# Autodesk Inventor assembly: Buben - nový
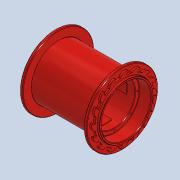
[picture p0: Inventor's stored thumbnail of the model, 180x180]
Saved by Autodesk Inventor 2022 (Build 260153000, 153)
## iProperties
Created: 2025-05
Part Number: Buben - nový
Document SubType Name: Assembly
Designer: jbart
Mass: 71047.9 g
Surface Area: 34761.7 cm^2
Volume: 71047.9 cm^3
Density: 1 g/cm^3
Author: jbart
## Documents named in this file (4)
- C:\Users\jbart\OneDrive\Dokumenty\Inventor\Převodovka navijáku\Buben - nový.iam
- C:\Users\jbart\OneDrive\Dokumenty\Inventor\Převodovka navijáku\Plášť bubnu.ipt
- C:\Users\jbart\OneDrive\Dokumenty\Inventor\Převodovka navijáku\Bočnice - levá.ipt
- C:\Users\jbart\OneDrive\Dokumenty\Inventor\Převodovka navijáku\Bočnice - pravá.ipt
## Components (3 placed, 3 different names)
1. Plášť bubnu:1 — Proti sobě:1, Proti sobě:2, Stejný směr:1, Proti sobě:3, Proti sobě:4, Stejný směr:2
2. Bočnice - levá:1 — Proti sobě:1, Proti sobě:2, Stejný směr:1
3. Bočnice - pravá:1 — Proti sobě:3, Proti sobě:4, Stejný směr:2
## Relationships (6: Mate 4, Flush 2)
- Proti sobě:1 [Mate]: Plášť bubnu:1 ↔ Bočnice - levá:1
- Proti sobě:2 [Mate]: Plášť bubnu:1 ↔ Bočnice - levá:1
- Stejný směr:1 [Flush]: Plášť bubnu:1 ↔ Bočnice - levá:1
- Proti sobě:3 [Mate]: Plášť bubnu:1 ↔ Bočnice - pravá:1
- Proti sobě:4 [Mate]: Plášť bubnu:1 ↔ Bočnice - pravá:1
- Stejný směr:2 [Flush]: Plášť bubnu:1 ↔ Bočnice - pravá:1
